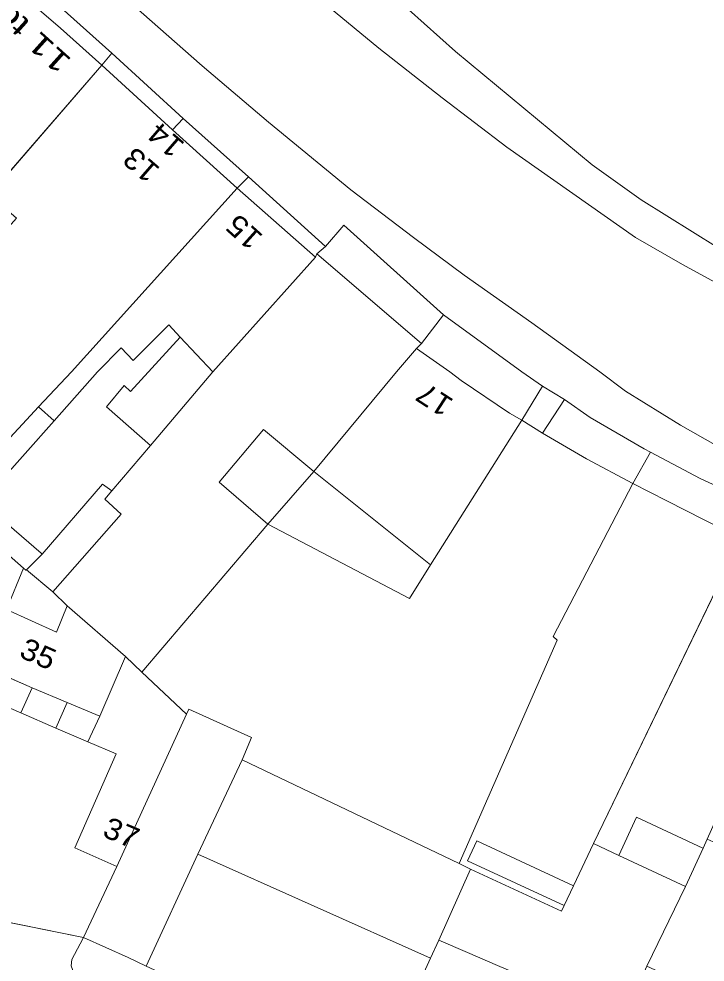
# Model space of a CAD drawing. Extents: x 528790 to 529292, y 179350 to 179856.
# Drawn here: x 529148.9 to 529197.1, y 179458.5 to 179524.8 of the extents above; entities that cross this region are included whole.
import ezdxf

# ---------------------------------------------------------------- set-up
doc = ezdxf.new("R2010")
doc.units = 0
doc.header["$LTSCALE"] = 0.6
doc.layers.add('1', color=7, linetype='Continuous', lineweight=13)
doc.layers.add('2', color=7, linetype='Continuous', lineweight=13)
doc.layers.add('5', color=7, linetype='Continuous')

msp = doc.modelspace()

# ---------------------------------------------------------------- linework, layer by layer
at = {"layer": '1'}
for points in [[(529139.7, 179540.9), (529161.75, 179521.5), (529166.4, 179517.55), (529172.2, 179512.8), (529176.6, 179509.45), (529180.15, 179506.8), (529184.9, 179503.45), (529189.7, 179500), (529191.5, 179498.65), (529195.35, 179496.25), (529199.7, 179493.8), (529204.05, 179491.65), (529212.55, 179488.2), (529224, 179483.65), (529235.05, 179479.15), (529236, 179478.25), (529236.2, 179477.8), (529236.4, 179477.3), (529236.55, 179476.8), (529236.55, 179476.4), (529236.5, 179476), (529236.4, 179475.55), (529240, 179473.8)], [(529232.55, 179473.5), (529234, 179476.7), (529236.4, 179475.55), (529236.5, 179476), (529236.55, 179476.4), (529236.55, 179476.8), (529236.4, 179477.3), (529236.2, 179477.8), (529236, 179478.25), (529235.05, 179479.15), (529224, 179483.65), (529212.55, 179488.2), (529204.05, 179491.65), (529199.7, 179493.8), (529195.35, 179496.25), (529191.5, 179498.65), (529189.7, 179500), (529184.9, 179503.45), (529180.15, 179506.8), (529176.6, 179509.45), (529172.2, 179512.8), (529166.4, 179517.55), (529161.75, 179521.5), (529139.7, 179540.9)], [(529145.8, 179531), (529155.4, 179522.4), (529160.4, 179517.8), (529165, 179513.7), (529170.4, 179508.8), (529171.7, 179510.3), (529178.7, 179504), (529184.2, 179500), (529185.65, 179499), (529187.2, 179498.05), (529189, 179496.8), (529192.8, 179494.6), (529193.25, 179494.35), (529196.75, 179492.5), (529200.65, 179490.7)], [(529199.8, 179507.6), (529192.6, 179512.1), (529189.15, 179514.55), (529179.55, 179522.5), (529170.75, 179530.4)], [(529170.75, 179530.4), (529179.55, 179522.5), (529189.15, 179514.55), (529192.6, 179512.1), (529199.8, 179507.6)], [(529246.643, 179481.097), (529236.7, 179486.05), (529225.55, 179491.8), (529222.455, 179493.382), (529218.899, 179495.199), (529218.8, 179495.249), (529216.757, 179496.282), (529209.4, 179500), (529202.15, 179503.95), (529198.8, 179505.75), (529195.5, 179507.55), (529192.2, 179509.45), (529183.15, 179515.8), (529178.6, 179519.25), (529174.15, 179522.75), (529170.7, 179525.6)], [(529170.7, 179525.6), (529174.15, 179522.75), (529178.6, 179519.25), (529183.15, 179515.8), (529192.2, 179509.45), (529195.5, 179507.55), (529198.8, 179505.75)], [(529152.53, 179458.27), (529152.592, 179458.708), (529153.168, 179459.806), (529153.4, 179460.25), (529147, 179461.55)], [(529157.8, 179458.25), (529156.55, 179458.85), (529153.4, 179460.25), (529153.168, 179459.806), (529152.592, 179458.708), (529152.53, 179458.27)]]:
    msp.add_lwpolyline(points, dxfattribs=at)
for points in [[(529145.75, 179530.8), (529145, 179530.05), (529145.8, 179529.3), (529151.8, 179524.15), (529154.7, 179521.55), (529155.4, 179522.4), (529145.8, 179531)], [(529146.8, 179512.45), (529154.7, 179521.55), (529151.8, 179524.15), (529145.8, 179529.3), (529145, 179530.05), (529137, 179521.05), (529141.55, 179517.1), (529129.6, 179503.4), (529127.169, 179505.521), (529124.9, 179507.5), (529122.2, 179509.8), (529120.7, 179511.15), (529117.95, 179507.95), (529116.75, 179506.55), (529115.35, 179505), (529119.4, 179501.5), (529120.95, 179503.25), (529124.5, 179500), (529130.929, 179494.567), (529134.9, 179498.8), (529136, 179500)], [(529160.4, 179517.8), (529155.4, 179522.4), (529154.7, 179521.55), (529159.65, 179517)], [(529150.25, 179497.55), (529152.55, 179500), (529164.2, 179512.9), (529159.65, 179517), (529154.7, 179521.55), (529146.8, 179512.45), (529148.7, 179510.8), (529139.08, 179500), (529136.6, 179497.25), (529134.9, 179498.8), (529130.929, 179494.567), (529138.05, 179488.55), (529140.6, 179491.55), (529142.2, 179490.3), (529142.8, 179491.8), (529144, 179490.8)], [(529159.65, 179517), (529164.2, 179512.9), (529165, 179513.7), (529160.4, 179517.8)], [(529170.4, 179508.8), (529165, 179513.7), (529164.2, 179512.9), (529169.7, 179508.05), (529169.8, 179508.3)], [(529169.7, 179508.05), (529164.2, 179512.9), (529152.55, 179500), (529150.25, 179497.55), (529151.35, 179496.55), (529154.4, 179500), (529156.05, 179501.7), (529156.9, 179500.8), (529159.4, 179503.3), (529160.208, 179502.44), (529162.5, 179500)], [(529169.8, 179508.3), (529177.15, 179502), (529178.7, 179504), (529171.7, 179510.3), (529170.4, 179508.8)], [(529175.4, 179500), (529176.8, 179501.65), (529177.15, 179502), (529169.8, 179508.3), (529169.7, 179508.05), (529162.5, 179500), (529158.109, 179494.835), (529155.4, 179491.65), (529154.9, 179491.05), (529156.05, 179490), (529151.25, 179484.55), (529152.25, 179483.55), (529156.35, 179480), (529157.5, 179478.9), (529166.35, 179489.3), (529162.95, 179492.25), (529166.05, 179495.95), (529169.6, 179493)], [(529185.65, 179499), (529184.2, 179500), (529178.7, 179504), (529177.15, 179502), (529176.8, 179501.65), (529179.15, 179500), (529179.95, 179499.4), (529183.35, 179497.1), (529184.2, 179496.6)], [(529160.208, 179502.44), (529159.4, 179503.3), (529156.9, 179500.8), (529156.05, 179501.7), (529154.4, 179500), (529151.35, 179496.55), (529147.252, 179491.97), (529146.25, 179490.85), (529150.434, 179487.257), (529150.5, 179487.2), (529154.75, 179492.1), (529155.4, 179491.65), (529158.109, 179494.835), (529155.019, 179497.544), (529156.256, 179499.037), (529156.719, 179498.613)], [(529162.5, 179500), (529160.208, 179502.44), (529156.719, 179498.613), (529156.256, 179499.037), (529155.019, 179497.544), (529158.109, 179494.835)], [(529184.2, 179496.6), (529183.35, 179497.1), (529179.95, 179499.4), (529179.15, 179500), (529176.8, 179501.65), (529175.4, 179500), (529169.6, 179493), (529177.8, 179486.45)], [(529184.2, 179496.6), (529185.65, 179495.7), (529187.2, 179498.05), (529185.65, 179499)], [(529187.2, 179498.05), (529185.65, 179495.7), (529188.75, 179493.9), (529192, 179492.15), (529193.25, 179494.35), (529192.8, 179494.6), (529189, 179496.8)], [(529149.4, 179486.1), (529150.5, 179487.2), (529150.434, 179487.257), (529146.25, 179490.85), (529147.252, 179491.97), (529151.35, 179496.55), (529150.25, 179497.55), (529144, 179490.8), (529145.2, 179489.7), (529149.2, 179486.2), (529149.361, 179486.057)], [(529192, 179492.15), (529188.75, 179493.9), (529185.65, 179495.7), (529184.2, 179496.6), (529177.8, 179486.45), (529176.309, 179484.085), (529166.35, 179489.3), (529157.5, 179478.9), (529160.65, 179475.95), (529160.8, 179476.3), (529165.2, 179474.3), (529164.55, 179472.75), (529179.8, 179465.45), (529186.7, 179481.15), (529186.4, 179481.4)], [(529169.6, 179493), (529166.05, 179495.95), (529162.95, 179492.25), (529166.35, 179489.3)], [(529199.6, 179488.3), (529200.65, 179490.7), (529196.75, 179492.5), (529193.25, 179494.35), (529192, 179492.15), (529194.4, 179490.95)], [(529177.8, 179486.45), (529169.6, 179493), (529166.35, 179489.3), (529176.309, 179484.085)], [(529151.25, 179484.55), (529156.05, 179490), (529154.9, 179491.05), (529155.4, 179491.65), (529154.75, 179492.1), (529150.5, 179487.2), (529149.4, 179486.1)], [(529199.6, 179488.3), (529194.4, 179490.95), (529192, 179492.15), (529186.4, 179481.4), (529186.7, 179481.15), (529179.8, 179465.45), (529180.6, 179465.05), (529187, 179462.1), (529187.184, 179462.499), (529180.39, 179465.646), (529181.035, 179467.038), (529187.829, 179463.891), (529189.25, 179466.85)], [(529144, 179490.8), (529142.8, 179491.8), (529142.2, 179490.3), (529141.06, 179487.63), (529138.9, 179482.55), (529149.8, 179477.8), (529152.259, 179476.764), (529154.55, 179475.8), (529156.35, 179480), (529152.25, 179483.55), (529151.5, 179481.7), (529148, 179483.3), (529149.2, 179486.2), (529145.2, 179489.7)], [(529198.94, 179470.979), (529199.95, 179473.2), (529205.4, 179484.95), (529205.8, 179485.8), (529205.65, 179485.85), (529203.05, 179486.9), (529199.6, 179488.3), (529189.25, 179466.85), (529191.02, 179466.027), (529192.267, 179468.708), (529196.924, 179466.543), (529196.947, 179466.532), (529197.23, 179467.164)], [(529149.2, 179486.2), (529148, 179483.3), (529151.5, 179481.7), (529152.25, 179483.55), (529151.25, 179484.55), (529149.4, 179486.1), (529149.361, 179486.057)], [(529203.704, 179467.191), (529210.6, 179482.95), (529209.35, 179483.45), (529205.4, 179484.95), (529199.95, 179473.2), (529198.94, 179470.979), (529201.672, 179469.755), (529199.962, 179465.94), (529197.23, 179467.164), (529196.947, 179466.532), (529195.7, 179463.85), (529193, 179458.25), (529197.8, 179456.05), (529199.05, 179456.55), (529199.55, 179457.7), (529201.924, 179463.125)], [(529149.8, 179477.8), (529138.9, 179482.55), (529138.4, 179481.4), (529136.6, 179482.1), (529134.8, 179477.6), (529136.5, 179476.8), (529145.9, 179472.8), (529147, 179475.3), (529147.6, 179476.65), (529149, 179476.05)], [(529156.35, 179480), (529154.55, 179475.8), (529153.7, 179474), (529155.7, 179473.15), (529152.8, 179466.55), (529155.75, 179465.25), (529160.65, 179475.95), (529157.5, 179478.9)], [(529152.259, 179476.764), (529149.8, 179477.8), (529149, 179476.05), (529151.472, 179474.972)], [(529154.55, 179475.8), (529152.259, 179476.764), (529151.472, 179474.972), (529153.7, 179474)], [(529155.75, 179465.25), (529152.8, 179466.55), (529155.7, 179473.15), (529153.7, 179474), (529151.472, 179474.972), (529149, 179476.05), (529147.6, 179476.65), (529147, 179475.3), (529147.95, 179474.95), (529146.95, 179472.4), (529146.4, 179471.1), (529146.25, 179470.85), (529144.95, 179467.8), (529144.2, 179466.15), (529143.55, 179464.45), (529146.8, 179463), (529146.4, 179461.8), (529147, 179461.55), (529153.4, 179460.25)], [(529157.8, 179458.25), (529161.45, 179466.1), (529164.55, 179472.75), (529165.2, 179474.3), (529160.8, 179476.3), (529160.65, 179475.95), (529155.75, 179465.25), (529153.4, 179460.25), (529156.55, 179458.85)], [(529179.8, 179465.45), (529164.55, 179472.75), (529161.45, 179466.1), (529177.8, 179458.8), (529178.371, 179460.076), (529180.6, 179465.05)], [(529195.7, 179463.85), (529196.947, 179466.532), (529196.924, 179466.543), (529192.267, 179468.708), (529191.02, 179466.027)], [(529195.7, 179463.85), (529191.02, 179466.027), (529189.25, 179466.85), (529187.829, 179463.891), (529187.184, 179462.499), (529187, 179462.1), (529180.6, 179465.05), (529178.371, 179460.076), (529180.398, 179459.204), (529182.5, 179458.3), (529186.8, 179456.45), (529185.9, 179454.3), (529184.6, 179454.9), (529184.15, 179453.8), (529179, 179456.05), (529176.939, 179456.951), (529174.05, 179450.75), (529186.95, 179444.8), (529193, 179458.25)], [(529187.184, 179462.499), (529187.829, 179463.891), (529181.035, 179467.038), (529180.39, 179465.646)], [(529177.8, 179458.8), (529161.45, 179466.1), (529157.8, 179458.25), (529162.8, 179455.95), (529164.65, 179455.1), (529174.05, 179450.75), (529176.939, 179456.951)], [(529186.8, 179456.45), (529182.5, 179458.3), (529180.398, 179459.204), (529178.371, 179460.076), (529177.8, 179458.8), (529176.939, 179456.951), (529179, 179456.05), (529184.15, 179453.8), (529184.6, 179454.9), (529185.9, 179454.3)]]:
    msp.add_lwpolyline(points, close=True, dxfattribs=at)
at = {"layer": '2'}
for p, q in [((529154.7, 179521.55), (529155.4, 179522.4)), ((529155.4, 179522.4), (529160.4, 179517.8)), ((529146.8, 179512.45), (529154.7, 179521.55)), ((529159.65, 179517), (529154.7, 179521.55)), ((529159.65, 179517), (529160.4, 179517.8)), ((529160.4, 179517.8), (529165, 179513.7)), ((529164.2, 179512.9), (529159.65, 179517)), ((529164.2, 179512.9), (529165, 179513.7)), ((529165, 179513.7), (529170.4, 179508.8)), ((529169.7, 179508.05), (529164.2, 179512.9)), ((529170.4, 179508.8), (529169.8, 179508.3)), ((529169.7, 179508.05), (529162.5, 179500)), ((529169.8, 179508.3), (529169.7, 179508.05)), ((529177.15, 179502), (529169.8, 179508.3)), ((529177.15, 179502), (529178.7, 179504)), ((529162.5, 179500), (529160.208, 179502.44)), ((529176.8, 179501.65), (529177.15, 179502)), ((529162.5, 179500), (529158.109, 179494.835)), ((529185.65, 179499), (529184.2, 179496.6)), ((529185.65, 179499), (529187.2, 179498.05)), ((529187.2, 179498.05), (529185.65, 179495.7)), ((529144, 179490.8), (529150.25, 179497.55)), ((529151.35, 179496.55), (529150.25, 179497.55)), ((529184.2, 179496.6), (529177.8, 179486.45)), ((529184.2, 179496.6), (529185.65, 179495.7)), ((529158.109, 179494.835), (529155.4, 179491.65)), ((529193.25, 179494.35), (529192, 179492.15)), ((529169.6, 179493), (529166.35, 179489.3)), ((529169.6, 179493), (529177.8, 179486.45)), ((529157.5, 179478.9), (529166.35, 179489.3)), ((529199.6, 179488.3), (529189.25, 179466.85)), ((529149.4, 179486.1), (529150.5, 179487.2)), ((529151.25, 179484.55), (529149.4, 179486.1)), ((529151.25, 179484.55), (529152.25, 179483.55)), ((529156.35, 179480), (529152.25, 179483.55)), ((529138.9, 179482.55), (529149.8, 179477.8)), ((529154.55, 179475.8), (529156.35, 179480)), ((529157.5, 179478.9), (529156.35, 179480)), ((529160.65, 179475.95), (529157.5, 179478.9)), ((529149.8, 179477.8), (529149, 179476.05)), ((529149.8, 179477.8), (529152.259, 179476.764)), ((529151.472, 179474.972), (529152.259, 179476.764)), ((529152.259, 179476.764), (529154.55, 179475.8)), ((529149, 179476.05), (529151.472, 179474.972)), ((529153.7, 179474), (529154.55, 179475.8)), ((529155.75, 179465.25), (529160.65, 179475.95)), ((529151.472, 179474.972), (529153.7, 179474)), ((529164.55, 179472.75), (529161.45, 179466.1)), ((529179.8, 179465.45), (529164.55, 179472.75)), ((529189.25, 179466.85), (529187.829, 179463.891)), ((529189.25, 179466.85), (529191.02, 179466.027)), ((529197.23, 179467.164), (529196.947, 179466.532)), ((529161.45, 179466.1), (529157.8, 179458.25)), ((529161.45, 179466.1), (529177.8, 179458.8)), ((529196.947, 179466.532), (529195.7, 179463.85)), ((529180.6, 179465.05), (529179.8, 179465.45)), ((529195.7, 179463.85), (529191.02, 179466.027)), ((529155.75, 179465.25), (529153.4, 179460.25)), ((529178.371, 179460.076), (529180.6, 179465.05)), ((529187.829, 179463.891), (529187.184, 179462.499)), ((529195.7, 179463.85), (529193, 179458.25)), ((529147, 179461.55), (529153.4, 179460.25)), ((529177.8, 179458.8), (529178.371, 179460.076)), ((529177.8, 179458.8), (529176.939, 179456.951))]:
    msp.add_line(p, q, dxfattribs=at)
for points in [[(529216.757, 179496.282), (529209.4, 179500), (529202.15, 179503.95), (529198.8, 179505.75), (529195.5, 179507.55), (529192.2, 179509.45), (529183.15, 179515.8), (529178.6, 179519.25), (529174.15, 179522.75), (529170.7, 179525.6), (529167.35, 179528.55), (529164.05, 179531.6), (529160.95, 179534.9), (529159.4, 179536.65), (529156, 179541.5), (529155.5, 179542.2), (529154.95, 179542.9), (529154.4, 179543.65), (529154, 179544.4), (529153.6, 179545.7), (529153.4, 179546.3), (529153.38, 179546.67)], [(529138, 179542.15), (529139.7, 179540.9), (529161.75, 179521.5), (529166.4, 179517.55), (529172.2, 179512.8), (529176.6, 179509.45), (529180.15, 179506.8), (529184.9, 179503.45), (529189.7, 179500), (529191.5, 179498.65), (529195.35, 179496.25), (529199.7, 179493.8), (529204.05, 179491.65), (529212.55, 179488.2), (529224, 179483.65), (529235.05, 179479.15), (529236, 179478.25), (529236.2, 179477.8), (529236.4, 179477.3), (529236.55, 179476.8), (529236.55, 179476.4), (529236.5, 179476), (529236.4, 179475.55)], [(529145.75, 179530.8), (529145.8, 179531), (529155.4, 179522.4)], [(529199.8, 179507.6), (529192.6, 179512.1), (529189.15, 179514.55), (529179.55, 179522.5), (529170.75, 179530.4)], [(529154.7, 179521.55), (529151.8, 179524.15), (529145.8, 179529.3), (529145, 179530.05)], [(529150.25, 179497.55), (529152.55, 179500), (529164.2, 179512.9)], [(529170.4, 179508.8), (529171.7, 179510.3), (529178.7, 179504)], [(529178.7, 179504), (529184.2, 179500), (529185.65, 179499)], [(529160.208, 179502.44), (529159.4, 179503.3), (529156.9, 179500.8), (529156.05, 179501.7), (529154.4, 179500), (529151.35, 179496.55)], [(529160.208, 179502.44), (529156.719, 179498.613), (529156.256, 179499.037), (529155.019, 179497.544), (529158.109, 179494.835)], [(529169.6, 179493), (529175.4, 179500), (529176.8, 179501.65)], [(529184.2, 179496.6), (529183.35, 179497.1), (529179.95, 179499.4), (529179.15, 179500), (529176.8, 179501.65)], [(529187.2, 179498.05), (529189, 179496.8), (529192.8, 179494.6), (529193.25, 179494.35)], [(529150.5, 179487.2), (529150.434, 179487.257), (529146.25, 179490.85), (529147.252, 179491.97), (529151.35, 179496.55)], [(529166.35, 179489.3), (529162.95, 179492.25), (529166.05, 179495.95), (529169.6, 179493)], [(529185.65, 179495.7), (529188.75, 179493.9), (529192, 179492.15)], [(529193.25, 179494.35), (529196.75, 179492.5), (529200.65, 179490.7)], [(529150.5, 179487.2), (529154.75, 179492.1), (529155.4, 179491.65)], [(529192, 179492.15), (529186.4, 179481.4), (529186.7, 179481.15), (529179.8, 179465.45)], [(529192, 179492.15), (529194.4, 179490.95), (529199.6, 179488.3)], [(529155.4, 179491.65), (529154.9, 179491.05), (529156.05, 179490), (529151.25, 179484.55)], [(529149.2, 179486.2), (529145.2, 179489.7), (529144, 179490.8)], [(529177.8, 179486.45), (529176.309, 179484.085), (529166.35, 179489.3)], [(529152.25, 179483.55), (529151.5, 179481.7), (529148, 179483.3), (529149.2, 179486.2)], [(529149.2, 179486.2), (529149.361, 179486.057), (529149.4, 179486.1)], [(529149, 179476.05), (529147.6, 179476.65), (529147, 179475.3)], [(529160.65, 179475.95), (529160.8, 179476.3), (529165.2, 179474.3), (529164.55, 179472.75)], [(529155.75, 179465.25), (529152.8, 179466.55), (529155.7, 179473.15), (529153.7, 179474)], [(529191.02, 179466.027), (529192.267, 179468.708), (529196.924, 179466.543), (529196.947, 179466.532)], [(529187.184, 179462.499), (529180.39, 179465.646), (529181.035, 179467.038), (529187.829, 179463.891)], [(529187.184, 179462.499), (529187, 179462.1), (529180.6, 179465.05)], [(529186.46, 179442.05), (529184.6, 179442.9), (529168.6, 179450.1), (529157.2, 179455.4), (529154.075, 179456.846), (529153.247, 179457.24), (529152.737, 179457.756), (529152.53, 179458.27), (529152.592, 179458.708), (529153.168, 179459.806), (529153.4, 179460.25)], [(529153.4, 179460.25), (529156.55, 179458.85), (529157.8, 179458.25)], [(529176.939, 179456.951), (529179, 179456.05), (529184.15, 179453.8), (529184.6, 179454.9), (529185.9, 179454.3), (529186.8, 179456.45), (529182.5, 179458.3), (529180.398, 179459.204), (529178.371, 179460.076)]]:
    msp.add_lwpolyline(points, dxfattribs=at)

# ---------------------------------------------------------------- texts
at = {"layer": '5'}
for s, rotation, width, p in [('11 to 12', 138, 1.4, (529152.65, 179521.92)), ('14', 139, 1.1, (529160.6, 179516.03)), ('13', 139, 1.1, (529158.87, 179514.28)), ('15', 138, 1.1, (529166.1, 179509.55)), ('17', 147, 1.1, (529179.5, 179498)), ('35', 336, 1.1, (529148.8, 179480)), ('37', 337, 1.1, (529154.65, 179467.4))]:
    msp.add_text(s, height=1.5, rotation=rotation, dxfattribs=dict(at, width=width)).set_placement(p)

doc.saveas('drawing.dxf')
